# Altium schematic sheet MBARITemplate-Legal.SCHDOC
size Legal; Organization: Monterey Bay Aquarium Research Institute; Address1: 7700 Sandholdt Rd; Address2: Moss Landing, CA 95039-9644; CompanyName: MBARI
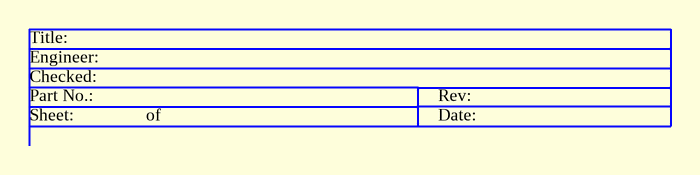
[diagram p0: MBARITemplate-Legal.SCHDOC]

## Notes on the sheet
- Sheet:
- Title:
- Engineer:
- Part No.:
- Checked:
- of
- Rev:
- Date:
